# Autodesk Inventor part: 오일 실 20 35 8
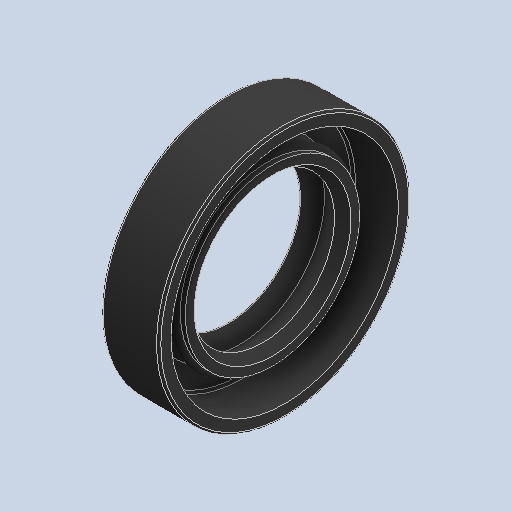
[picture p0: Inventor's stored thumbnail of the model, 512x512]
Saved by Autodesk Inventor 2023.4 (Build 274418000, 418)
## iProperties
Created: 2024-09
Part Number: 오일 실 20 35 8
Material: 고무
Description: 오일-실
Document SubType Name: Modeling
Designer: 11
Density: 0.93 g/cm^3
Appearance: 기본값
Author: jhkim
Sending System: Autodesk Inventor 2025
Preprocessor: ST-DEVELOPER v20
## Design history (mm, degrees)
node "오일 실 20 35 81"
node "솔리드1"
body "Solid1"
